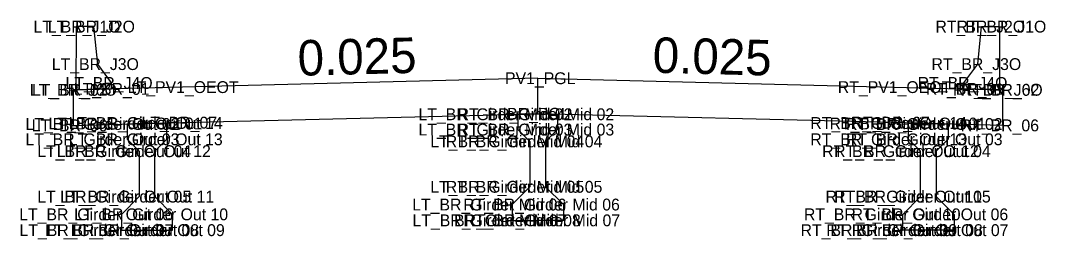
# Model space of a CAD drawing. Extents: x -26 to 2349090, y -10 to 844481.
# Drawn here: x 1128.16 to 1171.45, y 8022.02 to 8031.27 of the extents above; entities that cross this region are included whole.
import ezdxf

# ---------------------------------------------------------------- set-up
doc = ezdxf.new("R2010")
doc.units = 0
for name, color, linetype in [('Prop CMT Concrete Structures', 7, 'Continuous'), ('Prop XS Ditch Standard Text', 7, 'Continuous'), ('Scratch_Level_0', 7, 'Continuous')]:
    doc.layers.add(name, color=color, linetype=linetype)

msp = doc.modelspace()

# ---------------------------------------------------------------- linework, layer by layer
at = {"layer": 'Prop CMT Concrete Structures'}
for p, q in [((1130.501, 8031.01), (1130.5, 8028.343)), ((1131.251, 8031.01), (1130.501, 8031.01)), ((1131.418, 8029.427), (1131.251, 8031.01)), ((1168.582, 8029.427), (1168.749, 8031.01)), ((1168.749, 8031.01), (1169.499, 8031.01)), ((1169.499, 8031.01), (1169.5, 8028.343)), ((1131.999, 8028.631), (1131.418, 8029.427)), ((1168.001, 8028.631), (1168.582, 8029.427)), ((1132, 8028.381), (1131.999, 8028.631)), ((1150, 8028.831), (1135, 8028.456)), ((1150, 8027.331), (1150, 8028.831)), ((1150, 8028.831), (1165, 8028.456)), ((1150, 8027.331), (1150, 8028.831)), ((1168, 8028.381), (1168.001, 8028.631)), ((1135, 8028.456), (1130.375, 8028.34)), ((1130.375, 8028.34), (1130.375, 8026.84)), ((1130.5, 8028.343), (1132, 8028.381)), ((1165, 8028.456), (1169.625, 8028.34)), ((1169.5, 8028.343), (1168, 8028.381)), ((1169.625, 8028.34), (1169.625, 8026.84)), ((1135, 8026.956), (1150, 8027.331)), ((1150, 8027.331), (1149.167, 8027.31)), ((1149.167, 8027.31), (1149.167, 8026.664)), ((1150, 8027.331), (1150.833, 8027.31)), ((1165, 8026.956), (1150, 8027.331)), ((1150.833, 8027.31), (1150.833, 8026.664)), ((1130.375, 8026.84), (1135, 8026.956)), ((1133.5, 8026.918), (1132.667, 8026.898)), ((1132.667, 8026.898), (1132.667, 8026.252)), ((1134.333, 8026.939), (1133.5, 8026.918)), ((1134.333, 8026.252), (1134.333, 8026.939)), ((1169.625, 8026.84), (1165, 8026.956)), ((1165.667, 8026.939), (1166.5, 8026.918)), ((1165.667, 8026.252), (1165.667, 8026.939)), ((1166.5, 8026.918), (1167.333, 8026.898)), ((1167.333, 8026.898), (1167.333, 8026.252)), ((1149.167, 8026.664), (1149.667, 8026.164)), ((1150.833, 8026.664), (1150.333, 8026.164)), ((1132.667, 8026.252), (1133.167, 8025.752)), ((1133.833, 8025.752), (1134.333, 8026.252)), ((1149.667, 8026.164), (1149.667, 8024.248)), ((1150.333, 8026.164), (1150.333, 8024.248)), ((1166.167, 8025.752), (1165.667, 8026.252)), ((1167.333, 8026.252), (1166.833, 8025.752)), ((1133.167, 8025.752), (1133.167, 8023.835)), ((1133.833, 8023.835), (1133.833, 8025.752)), ((1166.167, 8023.835), (1166.167, 8025.752)), ((1166.833, 8025.752), (1166.833, 8023.835)), ((1149.667, 8024.248), (1148.917, 8023.498)), ((1150.333, 8024.248), (1151.083, 8023.498)), ((1133.167, 8023.835), (1132.417, 8023.085)), ((1134.583, 8023.085), (1133.833, 8023.835)), ((1165.417, 8023.085), (1166.167, 8023.835)), ((1166.833, 8023.835), (1167.583, 8023.085)), ((1148.917, 8023.498), (1148.917, 8022.831)), ((1151.083, 8023.498), (1151.083, 8022.831)), ((1132.417, 8023.085), (1132.417, 8022.418)), ((1134.583, 8022.418), (1134.583, 8023.085)), ((1165.417, 8022.418), (1165.417, 8023.085)), ((1167.583, 8023.085), (1167.583, 8022.418)), ((1132.417, 8022.418), (1133.5, 8022.418)), ((1133.5, 8022.418), (1134.583, 8022.418)), ((1148.917, 8022.831), (1150, 8022.831)), ((1151.083, 8022.831), (1150, 8022.831)), ((1166.5, 8022.418), (1165.417, 8022.418)), ((1167.583, 8022.418), (1166.5, 8022.418))]:
    msp.add_line(p, q, dxfattribs=at)

# ---------------------------------------------------------------- texts
at = {"layer": 'Prop XS Ditch Standard Text'}
for rotation, p in [(1.4321, (1139.88, 8028.933)), (358.5679, (1154.843, 8029.065))]:
    msp.add_text('0.025', height=1.5, rotation=rotation, dxfattribs=at).set_placement(p)
at = {"layer": 'Scratch_Level_0'}
for s, p in [('LT_BR_J1O', (1128.702, 8030.76)), ('LT_BR_J2O', (1129.31, 8030.76)), ('RT_BR_J2O', (1166.796, 8030.76)), ('RT_BR_J1O', (1167.688, 8030.76)), ('LT_BR_J3O', (1129.477, 8029.177)), ('RT_BR_J3O', (1166.63, 8029.177)), ('PV1_PGL', (1148.618, 8028.581)), ('LT_BR_J6O', (1128.547, 8028.093)), ('LT_BR_02', (1128.639, 8028.09)), ('LT_BR_J4O', (1130.058, 8028.381)), ('LT_BR_01', (1130.406, 8028.131)), ('LT_PV1_OEOT', (1132.685, 8028.206)), ('RT_PV1_OEOT', (1162.673, 8028.206)), ('RT_BR_J4O', (1166.048, 8028.381)), ('RT_BR_01', (1166.394, 8028.131)), ('RT_BR_J6O', (1167.535, 8028.093)), ('RT_BR_02', (1167.877, 8028.09)), ('LT_BR_Girder Out 02', (1128.364, 8026.648)), ('LT_BR_Girder Out 01', (1129.339, 8026.668)), ('LT_BR_Girder Out 14', (1130.192, 8026.689)), ('LT_BR_07', (1133.264, 8026.706)), ('LT_BR_Girder Mid 02', (1144.962, 8027.06)), ('RT_BR_Girder Mid 02', (1146.617, 8027.06)), ('BR_PGL', (1148.709, 8027.081)), ('RT_BR_Girder Out 14', (1161.513, 8026.689)), ('RT_BR_Girder Out 01', (1162.327, 8026.668)), ('RT_BR_Girder Out 02', (1163.018, 8026.648)), ('RT_BR_07', (1163.252, 8026.706)), ('LT_BR_06', (1128.627, 8026.59)), ('LT_BR_Girder Mid 03', (1144.962, 8026.414)), ('RT_BR_Girder Mid 03', (1146.617, 8026.414)), ('RT_BR_06', (1167.865, 8026.59)), ('LT_BR_Girder Out 03', (1128.364, 8026.002)), ('LT_BR_Girder Out 13', (1130.192, 8026.002)), ('LT_BR_Girder Mid 04', (1145.462, 8025.914)), ('RT_BR_Girder Mid 04', (1146.117, 8025.914)), ('RT_BR_Girder Out 13', (1161.513, 8026.002)), ('RT_BR_Girder Out 03', (1163.018, 8026.002)), ('LT_BR_Girder Out 04', (1128.864, 8025.502)), ('LT_BR_Girder Out 12', (1129.692, 8025.502)), ('RT_BR_Girder Out 12', (1162.013, 8025.502)), ('RT_BR_Girder Out 04', (1162.518, 8025.502)), ('LT_BR_Girder Mid 05', (1145.462, 8023.998)), ('RT_BR_Girder Mid 05', (1146.117, 8023.998)), ('LT_BR_Girder Out 05', (1128.864, 8023.585)), ('LT_BR_Girder Out 11', (1129.833, 8023.585)), ('LT_BR_Girder Mid 06', (1144.7, 8023.248)), ('RT_BR_Girder Mid 06', (1146.855, 8023.248)), ('RT_BR_Girder Out 11', (1162.155, 8023.585)), ('RT_BR_Girder Out 05', (1162.518, 8023.585)), ('LT_BR_Girder Out 06', (1128.102, 8022.835)), ('LT_BR_Girder Out 10', (1130.422, 8022.835)), ('RT_BR_Girder Out 10', (1161.243, 8022.835)), ('RT_BR_Girder Out 06', (1163.257, 8022.835)), ('LT_BR_Girder Mid 07', (1144.712, 8022.581)), ('BR_Girder Mid 08', (1146.469, 8022.581)), ('RT_BR_Girder Mid 07', (1146.867, 8022.581)), ('LT_BR_Girder Out 07', (1128.114, 8022.168)), ('LT_BR_Girder Out 08', (1129.197, 8022.168)), ('LT_BR_Girder Out 09', (1130.28, 8022.168)), ('RT_BR_Girder Out 09', (1161.102, 8022.168)), ('RT_BR_Girder Out 08', (1162.185, 8022.168)), ('RT_BR_Girder Out 07', (1163.268, 8022.168))]:
    msp.add_text(s, height=0.5, dxfattribs=at).set_placement(p)

doc.saveas('drawing.dxf')
